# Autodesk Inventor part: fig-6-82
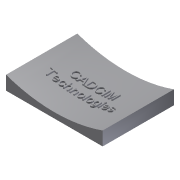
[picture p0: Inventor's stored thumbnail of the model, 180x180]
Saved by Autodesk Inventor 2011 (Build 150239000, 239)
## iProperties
Shininess: 64.0
Length Units: 11269
Angle Units: 11279
Time Units: 11290
Mass Units: 11283
Length Display Precision: 3
Angle Display Precision: 2
Compacted: True
Part Number: fig-6-82
Document SubType Name: Modeling
Created: 2002-12
Designer: deepak
Density: 1 g/cm^3
Density: 0.0
Volumn: 0.0
Area: 0.0
PropertySet Name: Model Information
Control State: 0
Master: False
Checked Out: False
Author: deepak
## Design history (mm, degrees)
sketch "Sketch1"
  geometry: L1 (-39.922, 33.786)-(30.103, 33.786); L2 (30.103, 33.786)-(30.103, -17.894); L3 (30.103, -17.894)-(-39.922, -17.894); L4 (-39.922, -17.894)-(-39.922, 33.786)
  constraints: 8 end point, 2 parallel, 1 horizontal, 1 perpendicular
extrude "Extrusion1" new body sketch "Sketch1" distance "d0" = 10; taper "d1" = 0 deg
workplane "Work Plane1"
sketch "Sketch2"
  geometry: L1 (-37.656, 15.034)-(26.28, 15.034); L2 (26.28, 15.034)-(26.28, 10.168); L3 (26.28, 10.168)-(-37.656, 10.168); L4 (-37.656, 10.168)-(-37.656, 15.034)
  constraints: 2 other
sketch "Sketch3"
  geometry: L1 (70.026, 10)-(0, 10) reference; A1 r 105 centre (35.013, 108.99) between (0, 10) and (70.026, 10)
  constraints: 2 point on circle, 1 centre point
  dimensions: "d5" = 105 radius of A1
extrude "Extrusion2" cut sketch "Sketch3" stored distance "d3" = 10; taper "d4" = 0 deg
emboss "Emboss4" sketch "Sketch2" dims "d14" = 1, "d15" = 0
body "Solid1"
other parameters: "d2" = 5
